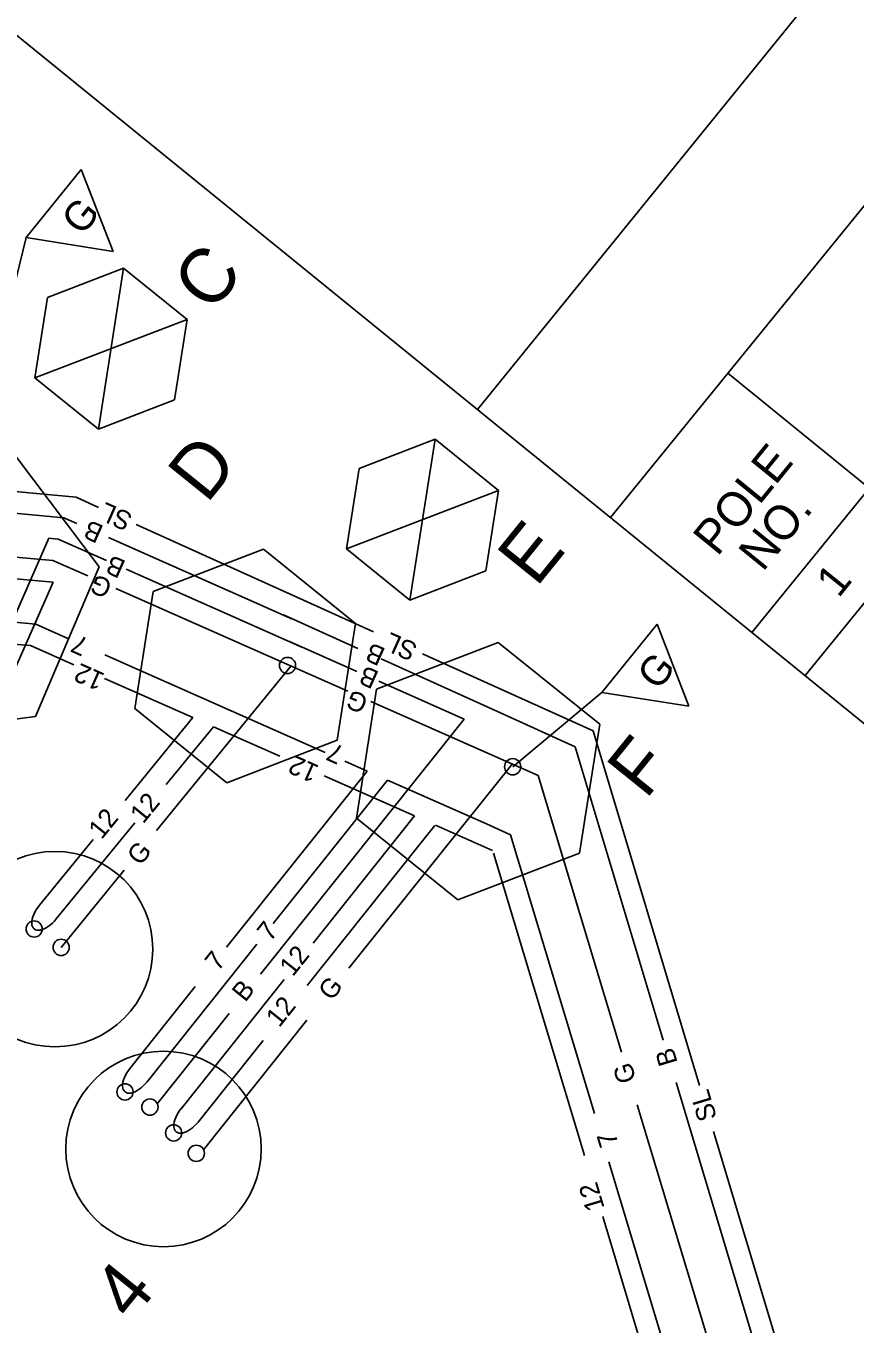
# Model space of a CAD drawing. Extents: x 592613 to 600223, y 4837996 to 4840103.
# Drawn here: x 592762.96 to 592777.46, y 4838919.81 to 4838942.52 of the extents above; entities that cross this region are included whole.
import ezdxf

# ---------------------------------------------------------------- set-up
doc = ezdxf.new("R2010")
doc.units = 0
for name, color, linetype in [('ENG_BORDER', 7, 'Continuous'), ('ENG_TITLEBLOCK', 7, 'Continuous'), ('ENG_TX_TITLEBLOCK', 7, 'Continuous'), ('Level 31', 7, 'Continuous'), ('Level 54', 7, 'Continuous'), ('TCS_ELEC-CHAMBER-NEW', 7, 'Continuous'), ('TCS_PLATE', 7, 'Continuous'), ('TCS_POLE-NEW', 7, 'Continuous'), ('TCS_WR_12', 7, 'Continuous'), ('TCS_WR_7', 7, 'Continuous'), ('TCS_WR_B', 7, 'Continuous'), ('TCS_WR_G', 7, 'Continuous'), ('TCS_WR_SL', 7, 'Continuous'), ('TCS_WR_W', 7, 'Continuous')]:
    doc.layers.add(name, color=color, linetype=linetype)

msp = doc.modelspace()

# ---------------------------------------------------------------- linework, layer by layer
at = {"layer": 'ENG_BORDER'}
for p, q in [((592790.401, 4838919.927), (592686.018, 4839004.737)), ((592773.181, 4838933.919), (592816.128, 4838986.778))]:
    msp.add_line(p, q, dxfattribs=at)
at = {"layer": 'ENG_TITLEBLOCK'}
msp.add_line((592770.854, 4838935.809), (592843.567, 4839025.495), dxfattribs=at)
at = {"layer": 'Level 31'}
for p, q in [((592775.654, 4838931.909), (592818.581, 4838984.742)), ((592776.582, 4838931.155), (592778.604, 4838933.643))]:
    msp.add_line(p, q, dxfattribs=at)
at = {"layer": 'Level 54'}
msp.add_line((592777.701, 4838934.439), (592775.233, 4838936.445), dxfattribs=at)
at = {"layer": 'TCS_ELEC-CHAMBER-NEW'}
for p, q in [((592763.336, 4838937.771), (592764.666, 4838938.283)), ((592764.666, 4838938.283), (592764.224, 4838935.468)), ((592764.666, 4838938.283), (592765.775, 4838937.388)), ((592763.115, 4838936.363), (592763.336, 4838937.771)), ((592763.115, 4838936.363), (592765.775, 4838937.388)), ((592765.775, 4838937.388), (592765.553, 4838935.98)), ((592764.224, 4838935.468), (592763.115, 4838936.363)), ((592765.553, 4838935.98), (592764.224, 4838935.468)), ((592762.523, 4838935.33), (592764.236, 4838933.056)), ((592768.784, 4838934.778), (592770.113, 4838935.291)), ((592770.113, 4838935.291), (592769.671, 4838932.475)), ((592770.113, 4838935.291), (592771.222, 4838934.395)), ((592768.563, 4838933.371), (592768.784, 4838934.778)), ((592768.563, 4838933.371), (592771.222, 4838934.395)), ((592771.222, 4838934.395), (592771.001, 4838932.988)), ((592765.18, 4838932.625), (592767.111, 4838933.369)), ((592767.111, 4838933.369), (592768.721, 4838932.069)), ((592769.671, 4838932.475), (592768.563, 4838933.371)), ((592764.236, 4838933.056), (592763.124, 4838930.437)), ((592771.001, 4838932.988), (592769.671, 4838932.475)), ((592764.859, 4838930.581), (592765.18, 4838932.625)), ((592768.721, 4838932.069), (592768.4, 4838930.025)), ((592769.09, 4838930.915), (592771.218, 4838931.734)), ((592771.218, 4838931.734), (592772.991, 4838930.302)), ((592768.736, 4838928.662), (592769.09, 4838930.915)), ((592766.469, 4838929.28), (592764.859, 4838930.581)), ((592763.124, 4838930.437), (592760.299, 4838930.09)), ((592772.991, 4838930.302), (592772.638, 4838928.05)), ((592768.4, 4838930.025), (592766.469, 4838929.28)), ((592770.51, 4838927.23), (592768.736, 4838928.662)), ((592772.638, 4838928.05), (592770.51, 4838927.23))]:
    msp.add_line(p, q, dxfattribs=at)
at = {"layer": 'TCS_PLATE'}
for p, q in [((592763.924, 4838940.009), (592762.964, 4838938.82)), ((592764.481, 4838938.577), (592763.924, 4838940.009)), ((592762.964, 4838938.82), (592764.481, 4838938.577)), ((592773.997, 4838932.055), (592773.03, 4838930.858)), ((592774.551, 4838930.619), (592773.997, 4838932.055)), ((592773.03, 4838930.858), (592774.551, 4838930.619))]:
    msp.add_line(p, q, dxfattribs=at)
at = {"layer": 'TCS_POLE-NEW'}
for centre in [(592763.465, 4838926.369), (592765.363, 4838922.872)]:
    msp.add_circle(centre, 1.71, dxfattribs=at)
at = {"layer": 'TCS_WR_12'}
for p, q in [((592762.734, 4838931.707), (592763.036, 4838931.679)), ((592763.036, 4838931.679), (592763.792, 4838931.344)), ((592764.329, 4838931.106), (592765.875, 4838930.42)), ((592764.69, 4838928.968), (592765.875, 4838930.42)), ((592765.411, 4838929.251), (592766.235, 4838930.26)), ((592766.235, 4838930.26), (592767.399, 4838929.744)), ((592768.175, 4838929.4), (592769.754, 4838928.7)), ((592763.488, 4838926.896), (592764.862, 4838928.578)), ((592769.754, 4838928.7), (592767.979, 4838926.473)), ((592770.109, 4838928.53), (592769.229, 4838927.429)), ((592770.117, 4838928.539), (592771.119, 4838928.095)), ((592763.194, 4838927.136), (592764.135, 4838928.289)), ((592771.133, 4838928.049), (592772.725, 4838922.756)), ((592769.228, 4838927.43), (592767.873, 4838925.73)), ((592767.473, 4838925.838), (592765.67, 4838923.575)), ((592767.107, 4838924.769), (592765.967, 4838923.338)), ((592773.045, 4838921.693), (592774.353, 4838917.343))]:
    msp.add_line(p, q, dxfattribs=at)
for centre, major_axis in [((592763.341, 4838927.016), (0.24, 0.294)), ((592765.824, 4838923.467), (0.237, 0.297))]:
    msp.add_ellipse(centre, major_axis=major_axis, ratio=0.5, start_param=1.570796, end_param=4.712389, dxfattribs=at)
at = {"layer": 'TCS_WR_7'}
for p, q in [((592761.916, 4838932.165), (592763.133, 4838932.052)), ((592763.133, 4838932.052), (592763.688, 4838931.806)), ((592764.338, 4838931.518), (592768.188, 4838929.81)), ((592768.532, 4838929.658), (592768.922, 4838929.485)), ((592768.922, 4838929.485), (592766.465, 4838926.402)), ((592769.281, 4838929.325), (592767.283, 4838926.819)), ((592769.281, 4838929.325), (592771.009, 4838928.559)), ((592771.009, 4838928.559), (592771.433, 4838928.371)), ((592771.433, 4838928.371), (592772.9, 4838923.492)), ((592766.994, 4838926.457), (592765.075, 4838924.049)), ((592765.918, 4838925.716), (592764.778, 4838924.286)), ((592773.154, 4838922.649), (592774.425, 4838918.421)), ((592773.154, 4838922.649), (592774.731, 4838917.405))]:
    msp.add_line(p, q, dxfattribs=at)
msp.add_ellipse((592764.927, 4838924.167), major_axis=(0.237, 0.297), ratio=0.5, start_param=1.570796, end_param=4.712389, dxfattribs=at)
at = {"layer": 'TCS_WR_B'}
for p, q in [((592761.528, 4838934.11), (592763.619, 4838933.915)), ((592763.619, 4838933.915), (592763.846, 4838933.814)), ((592763.356, 4838933.558), (592761.732, 4838929.873)), ((592763.356, 4838933.558), (592763.522, 4838933.542)), ((592763.522, 4838933.542), (592764.366, 4838933.168)), ((592764.401, 4838933.568), (592767.617, 4838932.142)), ((592764.709, 4838933.016), (592767.785, 4838931.652)), ((592767.463, 4838932.218), (592768.763, 4838931.629)), ((592767.564, 4838931.75), (592768.746, 4838931.225)), ((592769.168, 4838931.446), (592771.33, 4838930.468)), ((592769.131, 4838931.055), (592770.619, 4838930.395)), ((592770.619, 4838930.395), (592767.059, 4838925.928)), ((592771.33, 4838930.468), (592772.562, 4838929.911)), ((592772.562, 4838929.911), (592774.104, 4838924.777)), ((592766.513, 4838925.242), (592765.254, 4838923.664)), ((592774.328, 4838924.034), (592775.942, 4838918.661))]:
    msp.add_line(p, q, dxfattribs=at)
at = {"layer": 'TCS_WR_G'}
for p, q in [((592762.964, 4838938.82), (592761.62, 4838933.368)), ((592758.397, 4838933.622), (592763.425, 4838933.17)), ((592763.425, 4838933.17), (592764.038, 4838932.898)), ((592764.527, 4838932.681), (592768.584, 4838930.882)), ((592765.241, 4838928.442), (592767.592, 4838931.321)), ((592773.036, 4838930.866), (592771.47, 4838929.56)), ((592768.99, 4838930.702), (592771.916, 4838929.404)), ((592771.458, 4838929.607), (592768.602, 4838926.036)), ((592771.916, 4838929.404), (592773.371, 4838924.566)), ((592763.573, 4838926.399), (592764.677, 4838927.75)), ((592767.872, 4838925.123), (592766.064, 4838922.858)), ((592773.648, 4838923.644), (592775.613, 4838917.11))]:
    msp.add_line(p, q, dxfattribs=at)
at = {"layer": 'TCS_WR_SL'}
for p, q in [((592762.268, 4838934.422), (592763.834, 4838934.276)), ((592763.834, 4838934.276), (592764.228, 4838934.098)), ((592764.886, 4838933.801), (592769.036, 4838931.923)), ((592769.89, 4838931.536), (592772.875, 4838930.186)), ((592772.875, 4838930.186), (592774.739, 4838923.984)), ((592774.982, 4838923.176), (592776.758, 4838917.268))]:
    msp.add_line(p, q, dxfattribs=at)
at = {"layer": 'TCS_WR_W'}
for p, q in [((592758.038, 4838933.29), (592763.432, 4838932.787)), ((592763.432, 4838932.787), (592762.08, 4838929.72))]:
    msp.add_line(p, q, dxfattribs=at)
for centre in [(592767.532, 4838931.332), (592771.47, 4838929.56), (592763.101, 4838926.721), (592763.573, 4838926.399), (592764.689, 4838923.87), (592765.125, 4838923.605), (592765.541, 4838923.153), (592765.936, 4838922.796)]:
    msp.add_circle(centre, 0.142, dxfattribs=at)

# ---------------------------------------------------------------- texts
at = {"layer": 'ENG_TX_TITLEBLOCK'}
for s, height, rotation, p in [('POLE', 0.6, 50.9062, (592775.049, 4838933.224)), ('NO.', 0.6, 50.9062, (592775.843, 4838932.956)), ('1', 0.55, 51.1458, (592777.169, 4838932.499))]:
    msp.add_text(s, height=height, rotation=rotation, dxfattribs=at).set_placement(p)
at = {"layer": 'TCS_ELEC-CHAMBER-NEW'}
for s, p in [('C', (592766.204, 4838937.481)), ('D', (592766.119, 4838934.146)), ('E', (592771.883, 4838932.684)), ('F', (592773.799, 4838928.972))]:
    msp.add_text(s, height=0.95, rotation=51.0744, dxfattribs=at).set_placement(p)
at = {"layer": 'TCS_PLATE'}
for p in [(592763.94, 4838938.835), (592774.009, 4838930.876)]:
    msp.add_text('G', height=0.513, rotation=51.0744, dxfattribs=at).set_placement(p)
at = {"layer": 'TCS_POLE-NEW'}
msp.add_text('4', height=0.95, rotation=51.0744, dxfattribs=at).set_placement((592764.804, 4838919.838))
at = {"layer": 'TCS_WR_12'}
for rotation, p in [(156.0833, (592764.355, 4838931.181)), (156.0833, (592768.102, 4838929.57)), (50.77, (592765.008, 4838928.548)), (50.77, (592764.28, 4838928.274)), (51.3479, (592767.624, 4838925.874)), (51.3479, (592767.387, 4838924.984)), (106.7383, (592773.08, 4838921.842))]:
    msp.add_text('12', height=0.3325, rotation=rotation, dxfattribs=at).set_placement(p)
at = {"layer": 'TCS_WR_7'}
for height, rotation, p in [(0.332, 156.0833, (592764.075, 4838931.787)), (0.332, 156.0833, (592768.544, 4838929.893)), (0.333, 51.3479, (592767.232, 4838926.487)), (0.333, 51.3479, (592766.319, 4838925.967)), (0.333, 106.7383, (592773.323, 4838922.963))]:
    msp.add_text('7', height=height, rotation=rotation, dxfattribs=at).set_placement(p)
at = {"layer": 'TCS_WR_B'}
for height, rotation, p in [(0.333, 156.0833, (592764.336, 4838933.765)), (0.333, 156.0833, (592764.723, 4838933.151)), (0.333, 156.0833, (592769.265, 4838931.618)), (0.332, 156.0833, (592769.151, 4838931.215)), (0.333, 51.3479, (592766.792, 4838925.427)), (0.333, 106.7383, (592774.358, 4838924.384))]:
    msp.add_text('B', height=height, rotation=rotation, dxfattribs=at).set_placement(p)
at = {"layer": 'TCS_WR_G'}
for height, rotation, p in [(0.332, 156.0833, (592764.49, 4838932.797)), (0.332, 156.0833, (592768.967, 4838930.778)), (0.333, 50.77, (592764.956, 4838927.813)), (0.333, 51.3479, (592768.303, 4838925.449)), (0.333, 106.7383, (592773.634, 4838924.079))]:
    msp.add_text('G', height=height, rotation=rotation, dxfattribs=at).set_placement(p)
at = {"layer": 'TCS_WR_SL'}
for rotation, p in [(156.0833, (592764.843, 4838933.977)), (156.0833, (592769.827, 4838931.7)), (106.7383, (592775.044, 4838923.417))]:
    msp.add_text('SL', height=0.3325, rotation=rotation, dxfattribs=at).set_placement(p)

doc.saveas('drawing.dxf')
